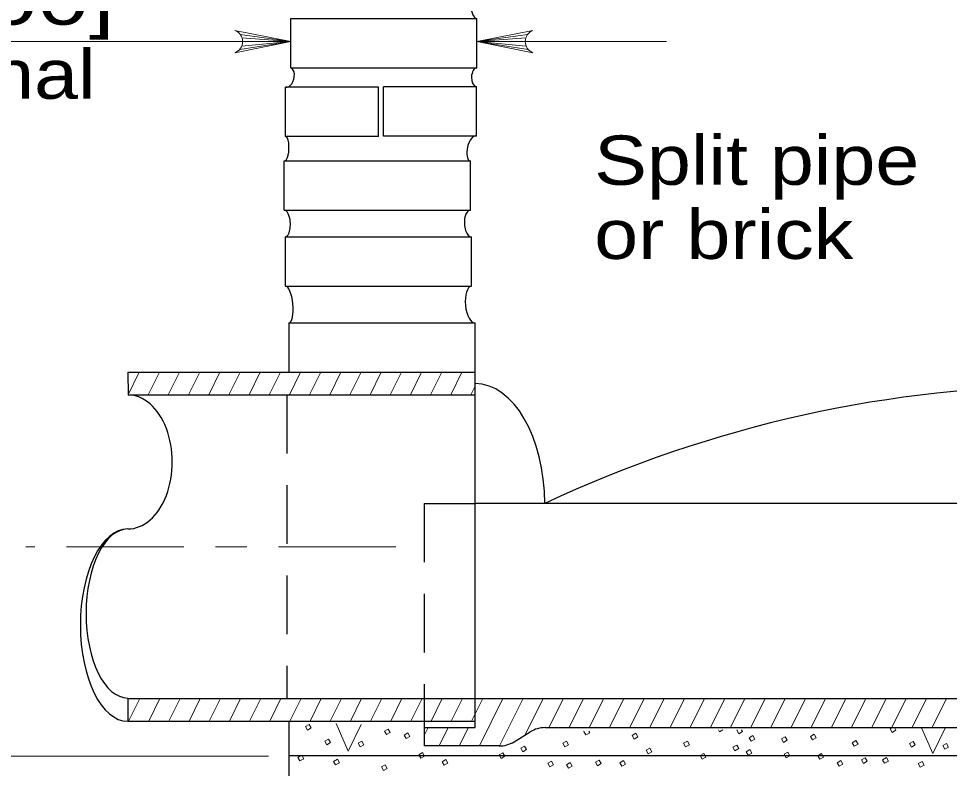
# Model space of a CAD drawing. Extents: x 1083.1 to 1117.1, y 697.4 to 741.4.
# Drawn here: x 1086.89 to 1089.838, y 729.966 to 732.34 of the extents above; entities that cross this region are included whole.
import ezdxf
from ezdxf.enums import TextEntityAlignment as Align

# ---------------------------------------------------------------- set-up
doc = ezdxf.new("R2010")
doc.units = 0
doc.header["$LTSCALE"] = 0.062
doc.linetypes.add('LONG_DASH_SHORT_DASH', pattern=[9.9, 6, -1.2, 1.5, -1.2])
doc.linetypes.add('MEDIUM_DASHED', pattern=[4.5, 3, -1.5])
doc.layers.add('1', color=7, linetype='Continuous', lineweight=13)

msp = doc.modelspace()

# ---------------------------------------------------------------- linework, layer by layer
at = {"layer": '1', "lineweight": 25}
for p, q in [((1087.75233, 732.18358), (1087.75233, 732.3395)), ((1088.34158, 732.18358), (1088.34158, 732.3395)), ((1088.02992, 732.12242), (1087.73525, 732.12242)), ((1088.02992, 731.9665), (1088.02992, 732.12242)), ((1088.33983, 732.12375), (1088.04525, 732.12375)), ((1088.04525, 731.96775), (1088.04525, 732.12375)), ((1088.33983, 731.96775), (1088.33983, 732.12375)), ((1088.33983, 731.96775), (1088.04525, 731.96775)), ((1088.32075, 731.73292), (1088.32075, 731.88892)), ((1087.7315, 731.73292), (1088.32075, 731.73292)), ((1088.3245, 731.49258), (1088.3245, 731.6485)), ((1087.73533, 731.49258), (1088.3245, 731.49258)), ((1088.33592, 731.22017), (1088.33592, 731.37617)), ((1087.23583, 731.22017), (1087.23642, 731.14808)), ((1087.23583, 731.22017), (1088.33592, 731.22017)), ((1088.33592, 730.09458), (1088.33592, 731.22017)), ((1087.23642, 731.14808), (1088.33592, 731.14808)), ((1092.05342, 730.80458), (1088.33592, 730.80458)), ((1087.23583, 730.18667), (1088.33592, 730.18667)), ((1087.23583, 730.18667), (1087.23583, 730.11458)), ((1087.23583, 730.18667), (1088.33592, 730.18667)), ((1088.33592, 730.18667), (1093.23292, 730.18667)), ((1087.23583, 730.11458), (1088.33592, 730.11458)), ((1087.74667, 729.50575), (1087.74667, 730.11458)), ((1088.17408, 730.09458), (1088.33592, 730.09458)), ((1088.17408, 730.09458), (1088.17408, 730.0365)), ((1088.55792, 730.09458), (1090.224, 730.09458)), ((1088.4595, 730.04983), (1088.51075, 730.08117)), ((1088.41233, 730.0365), (1088.17408, 730.0365)), ((1087.74667, 730.00642), (1092.69942, 730.00642))]:
    msp.add_line(p, q, dxfattribs=at)
at = {"layer": '1'}
for p, q in [((1087.59208, 732.28925), (1087.75233, 732.26683)), ((1087.5975, 732.27817), (1087.75233, 732.26683)), ((1088.50183, 732.28925), (1088.34158, 732.26683)), ((1088.49642, 732.27817), (1088.34158, 732.26683)), ((1087.75233, 732.26683), (1086.01308, 732.26683)), ((1087.59017, 732.24208), (1087.75233, 732.26683)), ((1087.59633, 732.25242), (1087.75233, 732.26683)), ((1087.59917, 732.26683), (1087.75233, 732.26683)), ((1088.9425, 732.26683), (1088.34158, 732.26683)), ((1088.49475, 732.26683), (1088.34158, 732.26683)), ((1088.49758, 732.25242), (1088.34158, 732.26683)), ((1088.50367, 732.24208), (1088.34158, 732.26683)), ((1087.23642, 731.14808), (1087.27192, 731.22017)), ((1087.23642, 731.14808), (1087.27192, 731.22017)), ((1087.30033, 731.14808), (1087.33583, 731.22017)), ((1087.36417, 731.14808), (1087.39975, 731.22017)), ((1087.42808, 731.14808), (1087.46358, 731.22017)), ((1087.492, 731.14808), (1087.5275, 731.22017)), ((1087.55583, 731.14808), (1087.59142, 731.22017)), ((1087.61975, 731.14808), (1087.65525, 731.22017)), ((1087.68358, 731.14808), (1087.71917, 731.22017)), ((1087.74658, 731.14633), (1087.783, 731.22017)), ((1087.81142, 731.14808), (1087.84692, 731.22017)), ((1087.87525, 731.14808), (1087.91083, 731.22017)), ((1087.93917, 731.14808), (1087.97467, 731.22017)), ((1088.00308, 731.14808), (1088.03858, 731.22017)), ((1088.06692, 731.14808), (1088.1025, 731.22017)), ((1088.13083, 731.14808), (1088.16633, 731.22017)), ((1088.19467, 731.14808), (1088.23025, 731.22017)), ((1088.25858, 731.14808), (1088.29408, 731.22017)), ((1088.3225, 731.14808), (1088.33592, 731.17533)), ((1087.23817, 730.11458), (1087.27375, 730.18667)), ((1087.30208, 730.11458), (1087.33767, 730.18667)), ((1087.366, 730.11458), (1087.4015, 730.18667)), ((1087.42983, 730.11458), (1087.46542, 730.18667)), ((1087.49375, 730.11458), (1087.52933, 730.18667)), ((1087.55758, 730.11458), (1087.59317, 730.18667)), ((1087.6215, 730.11458), (1087.65708, 730.18667)), ((1087.68542, 730.11458), (1087.72092, 730.18667)), ((1087.74925, 730.11458), (1087.78483, 730.18667)), ((1087.81317, 730.11458), (1087.84875, 730.18667)), ((1087.87708, 730.11458), (1087.91258, 730.18667)), ((1087.94092, 730.11458), (1087.9765, 730.18667)), ((1088.00483, 730.11458), (1088.04033, 730.18667)), ((1088.06867, 730.11458), (1088.10425, 730.18667)), ((1088.13258, 730.11458), (1088.16817, 730.18667)), ((1088.1965, 730.11458), (1088.232, 730.18667)), ((1088.26033, 730.11458), (1088.29592, 730.18667)), ((1088.32425, 730.11458), (1088.35983, 730.18667)), ((1088.34967, 730.0365), (1088.42367, 730.18667)), ((1088.41358, 730.0365), (1088.48758, 730.18667)), ((1088.49458, 730.07133), (1088.55142, 730.18667)), ((1088.56992, 730.09458), (1088.61533, 730.18667)), ((1088.63383, 730.09458), (1088.67925, 730.18667)), ((1088.69767, 730.09458), (1088.74308, 730.18667)), ((1088.76158, 730.09458), (1088.807, 730.18667)), ((1088.8255, 730.09458), (1088.87092, 730.18667)), ((1088.88933, 730.09458), (1088.93475, 730.18667)), ((1088.95325, 730.09458), (1088.99867, 730.18667)), ((1089.01717, 730.09458), (1089.0625, 730.18667)), ((1089.081, 730.09458), (1089.12642, 730.18667)), ((1089.14492, 730.09458), (1089.19033, 730.18667)), ((1089.20875, 730.09458), (1089.25417, 730.18667)), ((1089.27267, 730.09458), (1089.31808, 730.18667)), ((1089.33658, 730.09458), (1089.382, 730.18667)), ((1089.40042, 730.09458), (1089.44583, 730.18667)), ((1089.46433, 730.09458), (1089.50975, 730.18667)), ((1089.52825, 730.09458), (1089.57358, 730.18667)), ((1089.59208, 730.09458), (1089.6375, 730.18667)), ((1089.656, 730.09458), (1089.70142, 730.18667)), ((1089.71983, 730.09458), (1089.76525, 730.18667)), ((1089.78375, 730.09458), (1089.82917, 730.18667)), ((1088.17408, 730.06908), (1088.18667, 730.09458)), ((1088.22192, 730.0365), (1088.2505, 730.09458)), ((1088.28575, 730.0365), (1088.31442, 730.09458)), ((1089.16483, 730.08642), (1089.16742, 730.08783)), ((1089.65075, 730.09075), (1089.65433, 730.09275)), ((1088.68058, 730.08258), (1088.68117, 730.08292)), ((1086.6785, 730.00417), (1087.68192, 730.00417))]:
    msp.add_line(p, q, dxfattribs=at)
at = {"layer": '1', "linetype": 'MEDIUM_DASHED', "lineweight": 25}
for p, q in [((1087.73992, 731.14808), (1087.74, 730.18667)), ((1087.73992, 731.14808), (1087.74, 730.18667)), ((1088.17408, 730.80458), (1088.17408, 730.09458)), ((1088.17408, 730.80458), (1088.33592, 730.80458)), ((1088.17408, 730.80458), (1088.33592, 730.80458))]:
    msp.add_line(p, q, dxfattribs=at)
at = {"layer": '1', "linetype": 'LONG_DASH_SHORT_DASH'}
msp.add_line((1088.08525, 730.66742), (1086.91292, 730.66733), dxfattribs=at)
at = {"layer": '1', "lineweight": 25}
for points in [[(1087.75233, 732.3395), (1087.81675, 732.3395), (1088.34158, 732.3395)], [(1087.75233, 732.18358), (1087.82525, 732.18358), (1088.34158, 732.18358)], [(1088.02992, 731.9665), (1087.73525, 731.9665), (1087.73525, 732.12242)], [(1087.7315, 731.73292), (1087.7315, 731.88892), (1088.32075, 731.88892)], [(1087.73533, 731.49258), (1087.73533, 731.6485), (1088.3245, 731.6485)], [(1087.74667, 731.22017), (1087.74667, 731.37617), (1088.33592, 731.37617)]]:
    msp.add_lwpolyline(points, dxfattribs=at)
at = {"layer": '1'}
for points in [[(1087.57533, 732.23142), (1087.75233, 732.26683), (1087.57533, 732.30225)], [(1088.51858, 732.23142), (1088.34158, 732.26683), (1088.51858, 732.30225)], [(1087.8955, 730.10758), (1087.93367, 730.02), (1087.9745, 730.10392)], [(1089.17958, 730.088), (1089.183, 730.08192), (1089.17117, 730.07517), (1089.16483, 730.08642)], [(1089.66517, 730.09292), (1089.66892, 730.08617), (1089.65708, 730.0795), (1089.65075, 730.09075)], [(1089.75017, 730.09375), (1089.78558, 730.01267), (1089.82542, 730.0945)], [(1088.69592, 730.08308), (1088.69875, 730.078), (1088.68692, 730.07133), (1088.68058, 730.08258)], [(1089.12092, 730.08733), (1089.11025, 730.08125), (1089.10683, 730.08725)]]:
    msp.add_lwpolyline(points, dxfattribs=at)
for points in [[(1087.79883, 730.09808), (1087.81067, 730.10475), (1087.817, 730.0935), (1087.80517, 730.08683)], [(1088.04875, 730.0835), (1088.06067, 730.09017), (1088.067, 730.07892), (1088.05508, 730.07225)], [(1087.86, 730.05167), (1087.87183, 730.05842), (1087.87817, 730.04717), (1087.86633, 730.04042)], [(1088.11125, 730.071), (1088.12308, 730.07775), (1088.12942, 730.0665), (1088.11758, 730.05975)], [(1088.83292, 730.06975), (1088.84475, 730.0765), (1088.85108, 730.06525), (1088.83925, 730.0585)], [(1089.20383, 730.06242), (1089.21567, 730.06908), (1089.222, 730.05783), (1089.21017, 730.05117)], [(1089.30592, 730.05908), (1089.31775, 730.06583), (1089.32408, 730.05458), (1089.31225, 730.04783)], [(1089.39783, 730.06692), (1089.40967, 730.07358), (1089.416, 730.06233), (1089.40417, 730.05567)], [(1087.96575, 730.045), (1087.97758, 730.05167), (1087.98392, 730.04042), (1087.97208, 730.03375)], [(1088.48067, 730.02942), (1088.4925, 730.03617), (1088.49883, 730.02492), (1088.487, 730.01817)], [(1088.614, 730.04492), (1088.62583, 730.05158), (1088.63217, 730.04033), (1088.62033, 730.03367)], [(1088.87783, 730.02283), (1088.88967, 730.02958), (1088.896, 730.01833), (1088.88417, 730.01158)], [(1088.99633, 730.045), (1089.00817, 730.05167), (1089.0145, 730.0405), (1089.00267, 730.03375)], [(1089.15267, 730.03258), (1089.1645, 730.03933), (1089.17083, 730.02808), (1089.159, 730.02133)], [(1089.5305, 730.04658), (1089.54233, 730.05333), (1089.54867, 730.04208), (1089.53683, 730.03533)], [(1089.71183, 730.04433), (1089.72367, 730.05108), (1089.73, 730.03983), (1089.71817, 730.03308)], [(1089.81767, 730.03767), (1089.8295, 730.04433), (1089.83583, 730.03317), (1089.824, 730.02642)], [(1087.77475, 730.00017), (1087.78658, 730.00692), (1087.79292, 729.99567), (1087.78108, 729.98892)], [(1088.15733, 730.00875), (1088.16917, 730.0155), (1088.1755, 730.00425), (1088.16367, 729.9975)], [(1088.41233, 730.00817), (1088.42417, 730.01492), (1088.4305, 730.00367), (1088.41867, 729.997)], [(1089.04833, 730.00583), (1089.06017, 730.0125), (1089.0665, 730.00125), (1089.05467, 729.99458)], [(1089.19442, 730.01808), (1089.20625, 730.02475), (1089.21258, 730.01358), (1089.20075, 730.00683)], [(1089.31433, 730.01017), (1089.32617, 730.01692), (1089.3325, 730.00567), (1089.32067, 729.99892)], [(1089.42158, 730.00558), (1089.43342, 730.01233), (1089.43975, 730.00108), (1089.42792, 729.99433)], [(1089.55992, 729.9925), (1089.57175, 729.99925), (1089.57808, 729.988), (1089.56625, 729.98125)], [(1089.62658, 729.99283), (1089.63842, 729.99958), (1089.64475, 729.98833), (1089.63292, 729.98158)], [(1087.88767, 729.98775), (1087.8995, 729.99442), (1087.90583, 729.98325), (1087.894, 729.9765)], [(1088.0395, 729.96992), (1088.05133, 729.97667), (1088.05767, 729.96542), (1088.04583, 729.95867)], [(1088.23125, 729.98675), (1088.24308, 729.9935), (1088.24942, 729.98225), (1088.23758, 729.9755)], [(1088.56633, 729.98167), (1088.57817, 729.98833), (1088.5845, 729.97708), (1088.57267, 729.97042)], [(1088.62508, 729.97725), (1088.63692, 729.98392), (1088.64325, 729.97267), (1088.63142, 729.966)], [(1088.717, 729.985), (1088.72883, 729.99175), (1088.73517, 729.9805), (1088.72333, 729.97375)], [(1088.79458, 729.98333), (1088.80642, 729.99), (1088.81275, 729.97883), (1088.80092, 729.97208)], [(1089.48283, 729.98333), (1089.49467, 729.99), (1089.501, 729.97883), (1089.48917, 729.97208)], [(1089.73958, 729.98042), (1089.75142, 729.98708), (1089.75775, 729.97592), (1089.74592, 729.96917)]]:
    msp.add_lwpolyline(points, close=True, dxfattribs=at)
for centre, start, end in [((1087.56104, 732.26689), 292.08605, 67.91218), ((1088.53286, 732.26689), 112.08782, 247.91395)]:
    msp.add_arc(centre, 0.0382, start, end, dxfattribs=at)
at = {"layer": '1', "lineweight": 25}
for centre, major_axis, ratio, start_param, end_param in [((1088.33967, 732.38373), (0.00185, -0.0442), 0.403909, 3.1440839, 6.2856766), ((1087.7438, 732.153), (-0.00803, -0.03072), 0.587694, 6.2553219, 9.3969146), ((1088.3407, 732.15365), (-0.00082, -0.02992), 0.542892, 3.1388956, 6.2804882), ((1087.73339, 731.92768), (-0.00185, -0.0388), 0.331305, 6.2810191, 9.4226118), ((1088.33029, 731.92833), (0.00923, 0.03953), 0.473051, 6.2664694, 9.408062), ((1087.73341, 731.69073), (0.00185, -0.0422), 0.407962, 0.0026465, 3.1442392), ((1088.32265, 731.69073), (0.00182, -0.0422), 0.491373, 3.1450955, 6.2866882), ((1087.74098, 731.43436), (-0.00561, 0.05822), 0.302643, 3.1454771, 6.2870697), ((1088.33022, 731.43436), (0.00552, -0.05823), 0.428881, 3.1477204, 6.289313), ((1090.22398, 726.80542), (0, 4.37154), 0.944544, 5.8674479, 6.6989234), ((1088.33589, 730.80459), (0, 0.37925), 0.581343, 4.7123892, 6.2831855), ((1087.23587, 730.93581), (0, 0.21228), 0.663452, 3.1415925, 6.2831852), ((1087.23587, 730.41904), (0, 0.30449), 0.493973, 6.2831853, 9.4247779), ((1087.23587, 730.4559), (0, 0.26763), 0.493973, 6.2831853, 9.4247779), ((1088.55794, 729.99463), (0, 0.09994), 0.944544, 0.0000001, 0.5236033), ((1088.41232, 730.13643), (0, -0.09994), 0.944544, 6.2831658, 6.8067953)]:
    msp.add_ellipse(centre, major_axis=major_axis, ratio=ratio, start_param=start_param, end_param=end_param, dxfattribs=at)

# ---------------------------------------------------------------- texts
at = {"layer": '1'}
for s, width, p in [('8" [200]', 1.4, (1086.69538, 732.32025)), ('nominal', 1.2, (1086.69542, 732.08558))]:
    msp.add_text(s, height=0.156, dxfattribs=dict(at, width=width)).set_placement(p, align=Align.CENTER)
at = {"layer": '1', "width": 1.2}
for s, p in [('Split pipe', (1088.71308, 731.81333)), ('or brick', (1088.71308, 731.57867))]:
    msp.add_text(s, height=0.156, dxfattribs=at).set_placement(p)

doc.saveas('drawing.dxf')
